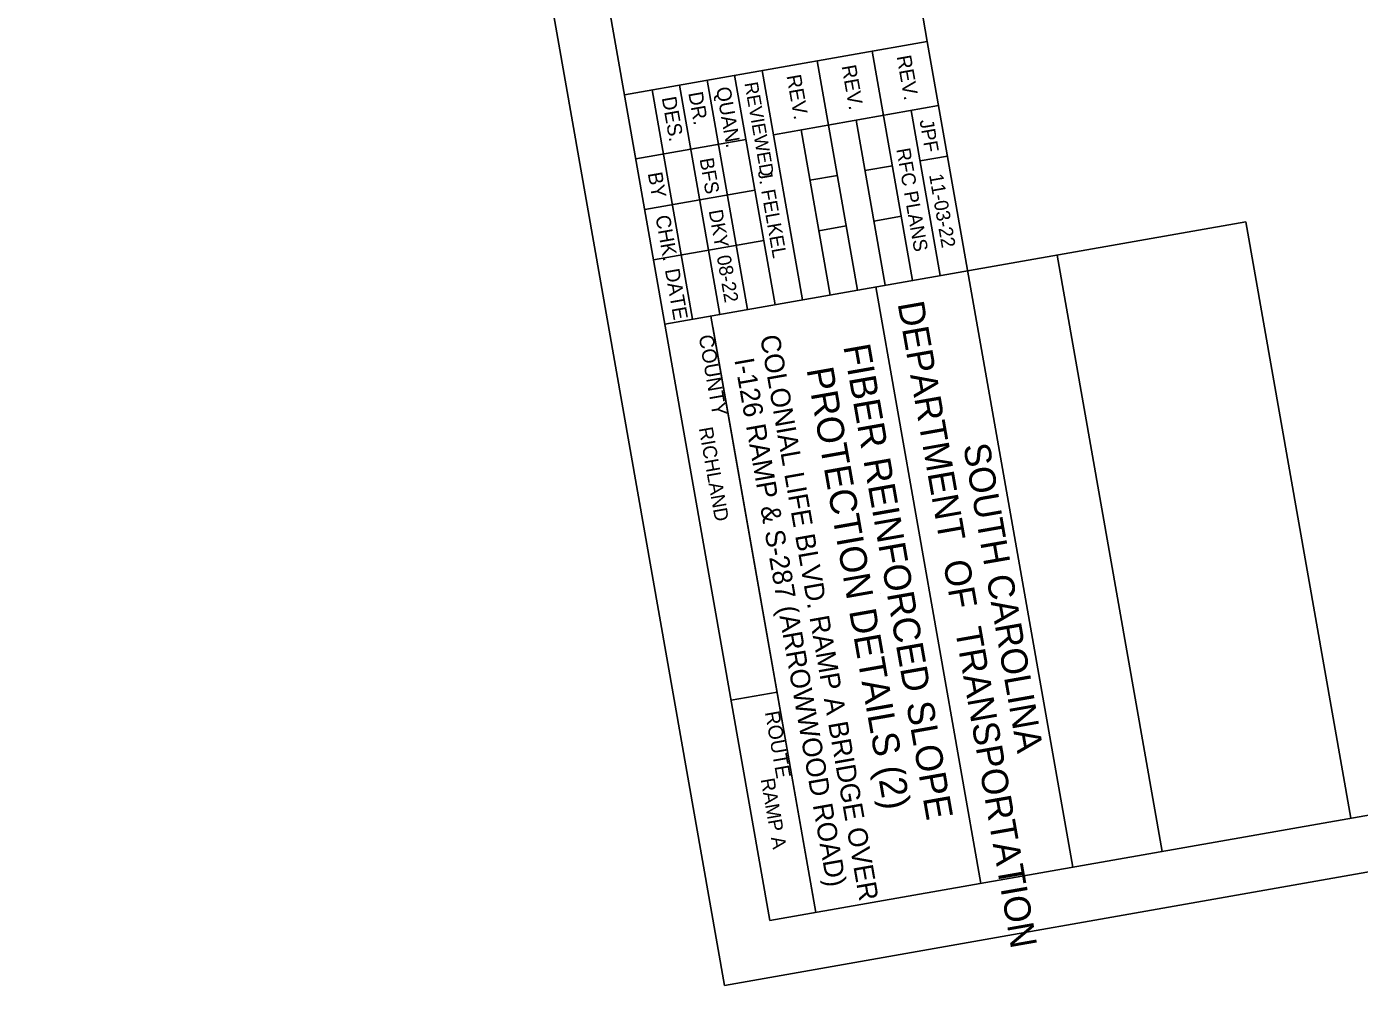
# Model space of a CAD drawing. Extents: x 1971280 to 1971503, y 796034 to 796348.
# Drawn here: x 1971279.6 to 1971374.9, y 796033.9 to 796102.5 of the extents above; entities that cross this region are included whole.
import ezdxf

# ---------------------------------------------------------------- set-up
doc = ezdxf.new("R2010")
doc.units = 0
for name, color, linetype in [('BR_BORDER LINES', 7, 'Continuous'), ('BR_TEXT', 7, 'Continuous'), ('Level 31', 7, 'Continuous')]:
    doc.layers.add(name, color=color, linetype=linetype)

msp = doc.modelspace()

# ---------------------------------------------------------------- linework, layer by layer
at = {"layer": 'BR_BORDER LINES'}
for p, q in [((1971286.058, 796303.806), (1971332.766, 796038.559)), ((1971336.584, 796143.739), (1971344.027, 796101.468)), ((1971322.36, 796097.652), (1971344.027, 796101.468)), ((1971344.027, 796101.468), (1971354.433, 796042.374)), ((1971336.148, 796100.08), (1971339.039, 796083.665)), ((1971340.088, 796100.774), (1971342.978, 796084.359)), ((1971330.239, 796099.039), (1971333.13, 796082.625)), ((1971332.209, 796099.386), (1971335.099, 796082.972)), ((1971326.3, 796098.346), (1971329.19, 796081.931)), ((1971328.269, 796098.693), (1971331.16, 796082.278)), ((1971324.33, 796097.999), (1971327.22, 796081.584)), ((1971344.837, 796096.871), (1971333.018, 796094.79)), ((1971342.867, 796096.525), (1971344.948, 796084.706)), ((1971338.928, 796095.831), (1971341.009, 796084.012)), ((1971331.048, 796094.443), (1971323.169, 796093.056)), ((1971334.988, 796095.137), (1971337.069, 796083.318)), ((1971343.503, 796092.913), (1971345.473, 796093.26)), ((1971339.563, 796092.22), (1971341.533, 796092.566)), ((1971335.624, 796091.526), (1971337.594, 796091.873)), ((1971331.684, 796090.832), (1971323.805, 796089.445)), ((1971325.25, 796081.237), (1971366.823, 796088.558)), ((1971340.199, 796088.608), (1971342.169, 796088.955)), ((1971366.823, 796088.558), (1971374.339, 796045.88)), ((1971336.26, 796087.915), (1971338.23, 796088.261)), ((1971332.32, 796087.221), (1971324.441, 796085.833)), ((1971353.314, 796086.177), (1971360.829, 796043.5)), ((1971340.352, 796083.897), (1971340.352, 796083.897)), ((1971340.352, 796083.896), (1971347.867, 796041.216)), ((1971328.533, 796081.815), (1971336.049, 796039.137)), ((1971328.669, 796081.047), (1971336.049, 796039.137)), ((1971332.766, 796038.559), (1971498.22, 796067.694)), ((1971329.991, 796054.317), (1971333.274, 796054.895))]:
    msp.add_line(p, q, dxfattribs=at)
at = {"layer": 'Level 31'}
for p, q in [((1971279.575, 796317.557), (1971329.522, 796033.921)), ((1971329.522, 796033.921), (1971502.855, 796064.444)), ((1971340.642, 796061.945), (1971340.642, 796061.945))]:
    msp.add_line(p, q, dxfattribs=at)

# ---------------------------------------------------------------- texts
at = {"layer": 'BR_TEXT'}
for s, height, p in [('REV.', 1.04, (1971341.824, 796100.392)), ('REV.', 1.04, (1971333.945, 796099.004)), ('REV.', 1.04, (1971337.884, 796099.698)), ('QUAN.', 1.04, (1971328.898, 796098.126)), ('REVIEWED', 0.96, (1971330.935, 796098.479)), ('DES.', 1.04, (1971325.017, 796097.432)), ('DR.', 1.04, (1971326.917, 796097.776)), ('JPF', 1, (1971343.465, 796095.801)), ('RFC PLANS', 1, (1971341.804, 796093.75)), ('BFS', 1, (1971327.726, 796093.047)), ('BY', 1.04, (1971324.017, 796092.025)), ('J. FELKEL', 1, (1971331.887, 796092.189)), ('11-03-22', 1, (1971344.15, 796091.908)), ('CHK.', 1.04, (1971324.57, 796088.947)), ('DKY', 1, (1971328.378, 796089.345)), ('08-22', 1, (1971328.952, 796086.084)), ('DATE', 1.04, (1971325.244, 796085.124)), ('DEPARTMENT  OF  TRANSPORTATION', 1.88696, (1971341.893, 796082.712)), ('COUNTY', 1.04, (1971327.661, 796080.385)), ('COLONIAL LIFE BLVD. RAMP A BRIDGE OVER', 1.4, (1971332.053, 796080.351)), ('FIBER REINFORCED SLOPE', 1.92, (1971338.011, 796079.65)), ('I-126 RAMP & S-287 (ARROWWOOD ROAD)', 1.4, (1971330.213, 796078.691)), ('PROTECTION DETAILS (2)', 1.92, (1971335.378, 796078)), ('RICHLAND', 1, (1971327.669, 796073.788)), ('SOUTH CAROLINA', 1.88696, (1971346.588, 796072.551)), ('ROUTE', 1.04, (1971332.402, 796053.464)), ('RAMP A', 1, (1971332.094, 796048.662))]:
    msp.add_text(s, height=height, rotation=279.98697, dxfattribs=at).set_placement(p)

doc.saveas('drawing.dxf')
